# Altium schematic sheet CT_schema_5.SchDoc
size 287 x 160 mm
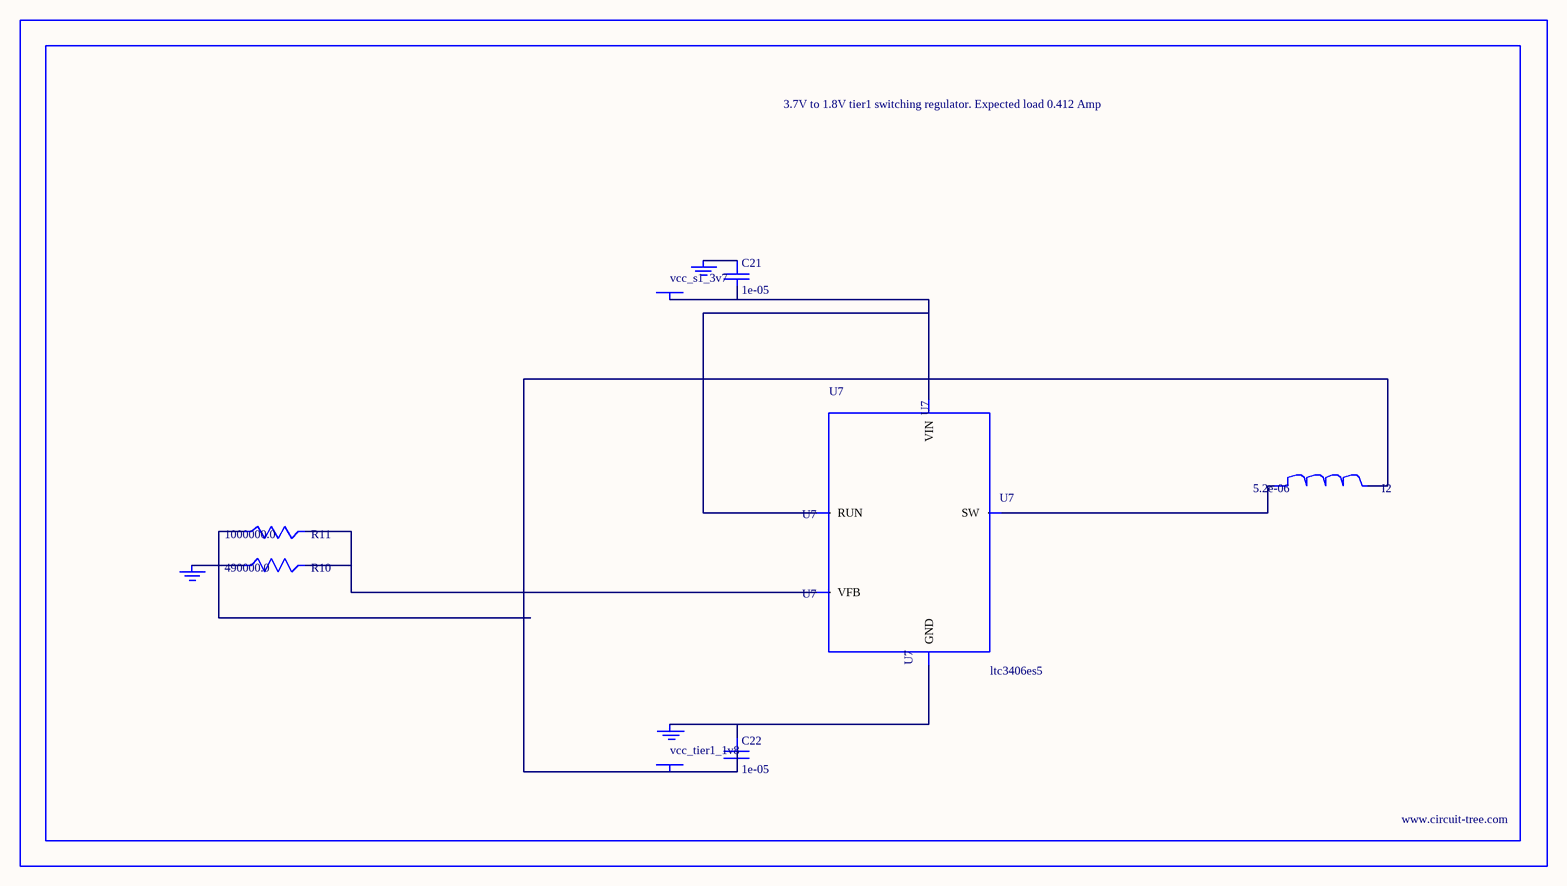
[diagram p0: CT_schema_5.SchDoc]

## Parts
BORDER4  (no value)
C21  1e-05  [C0805]
C22  1e-05  [C0805]
GND_INSTANCE_4_0  (no value)
GND_INSTANCE_4_1  (no value)
GND_INSTANCE_4_2  (no value)
I2  5.2e-06  [DR1040]
POWER_INSTANCE_4_0  vcc_tier1_1v8
POWER_INSTANCE_4_1  vcc_s1_3v7
R10  490000.0  [R0603]
R11  1000000.0  [R0603]
U7  ltc3406es5  [TSOT-23-5]

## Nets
NetC21_1: C21.1 GND_INSTANCE_4_1.0(GND)
NetC21_2: C21.2 POWER_INSTANCE_4_1.0(PWR) U7.1(RUN) U7.4(VIN)
NetC22_1: C22.1 GND_INSTANCE_4_0.0(GND) U7.2(GND)
NetC22_2: C22.2 I2.2 POWER_INSTANCE_4_0.0(PWR) R11.1
NetGND_INSTANCE_4_2_0: GND_INSTANCE_4_2.0(GND) R10.1
NetI2_1: I2.1 U7.3(SW)
NetR10_2: R10.2 R11.2 U7.5(VFB)

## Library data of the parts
BORDER4 = BORDER_PAGE4
C21 C22 = C0805C106K8RACTU
GND_INSTANCE_4_0-GND_INSTANCE_4_2 = GND
I2 = DR1040-5R2-R
POWER_INSTANCE_4_0 POWER_INSTANCE_4_1 = PWR
R10 = R10
R11 = RC0603JR-071ML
